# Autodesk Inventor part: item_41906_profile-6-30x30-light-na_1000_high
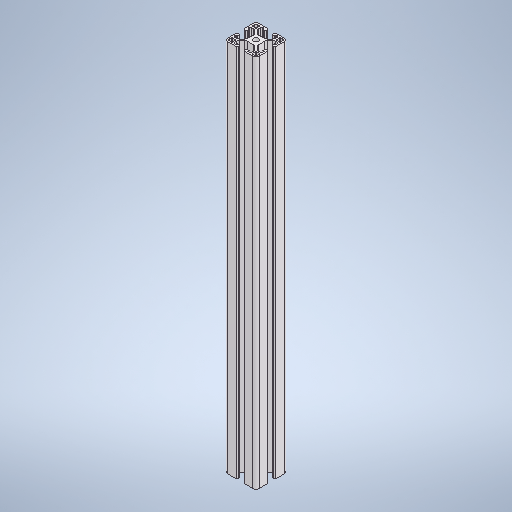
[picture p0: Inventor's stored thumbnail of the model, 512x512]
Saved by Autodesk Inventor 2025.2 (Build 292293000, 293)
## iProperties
Created: 2025-04
Part Number: item_41906_profile-6-30x30-light-na_1000_high
Material: Generic
Description: STEP AP214
Document SubType Name: Modeling
Designer: BennF
Authority: unknown authorization
Density: 1 g/cm^3
Appearance: Default
Company: CADClick - www.CADClick.com
Title: cctmp_E645AAE7-4D4E-402E-9FB8-C5FCD92D0650_2025_04_11_13_18_13_0061_50468..stp
Author: KiM GmbH
Revision Number: NONE
Preprocessor: Spatial InterOp 3D
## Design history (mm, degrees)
feature "item_0041906_Profil 6 30x30 leicht_L=1000_1"
thicken "Thicken1" dims "d0" = 642, "d1" = 640
body "Solid1"
